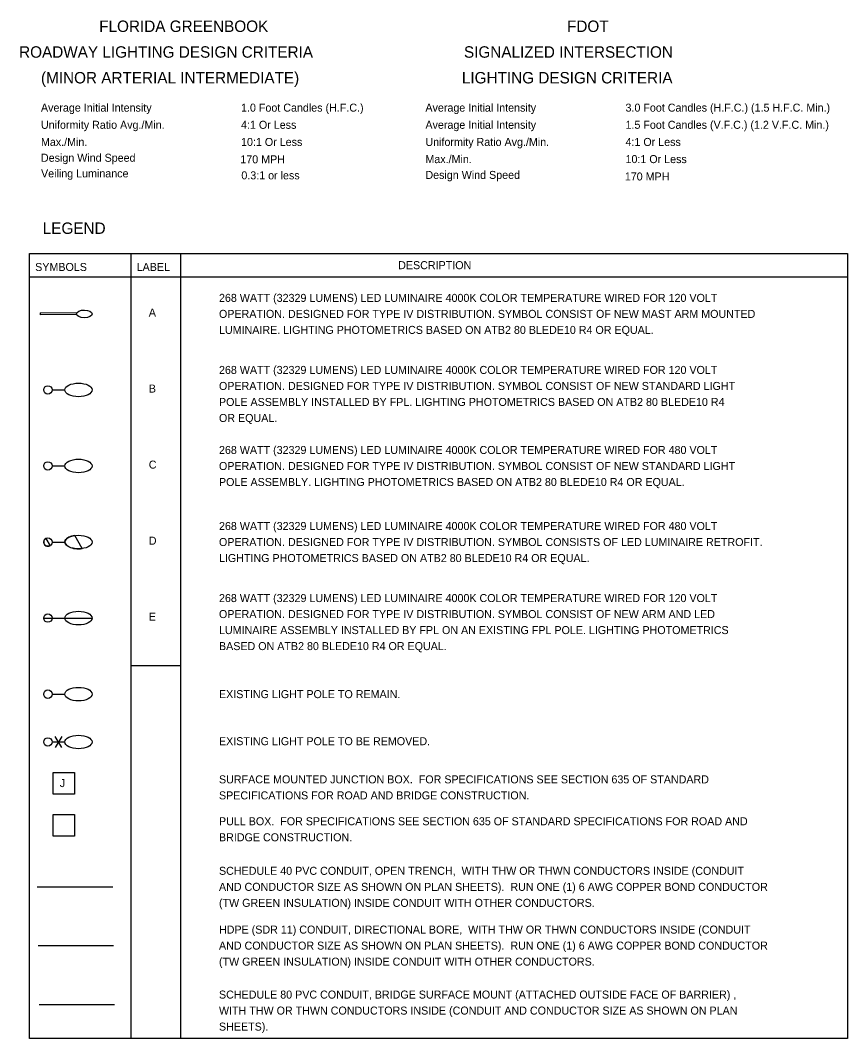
# Model space of a CAD drawing. Extents: x 0.1 to 21.4, y -0.2 to 9.3.
# Drawn here: x 0.15 to 7.38, y 0.37 to 9.27 of the extents above; entities that cross this region are included whole.
import ezdxf

# ---------------------------------------------------------------- set-up
doc = ezdxf.new("R2010")
doc.units = 0
for name, color, linetype in [('ConduitBM', 7, 'Continuous'), ('ConduitDB', 7, 'Continuous'), ('ConduitOT', 7, 'Continuous'), ('Luminaire', 7, 'Continuous'), ('PoleLight', 7, 'Continuous'), ('PoleLight_ep', 7, 'Continuous'), ('ScratchEle_dp', 7, 'Continuous'), ('SumBoxLines_dp', 7, 'Continuous'), ('TextLabel', 7, 'Continuous'), ('TextNotes', 7, 'Continuous')]:
    doc.layers.add(name, color=color, linetype=linetype)

msp = doc.modelspace()

# ---------------------------------------------------------------- linework, layer by layer
at = {"layer": 'ConduitBM'}
msp.add_line((0.3115, 0.6658), (0.9708, 0.6658), dxfattribs=at)
at = {"layer": 'ConduitDB'}
msp.add_line((0.3028, 1.1796), (0.9621, 1.1796), dxfattribs=at)
at = {"layer": 'ConduitOT'}
msp.add_line((0.294, 1.6935), (0.9534, 1.6935), dxfattribs=at)
at = {"layer": 'Luminaire'}
for p, q in [((0.3231, 6.6944), (0.3231, 6.713)), ((0.6391, 6.7089), (0.3231, 6.713)), ((0.6391, 6.6977), (0.3231, 6.6944))]:
    msp.add_line(p, q, dxfattribs=at)
msp.add_ellipse((0.7056, 6.7033), major_axis=(0.0675, -0.0001), ratio=0.5, dxfattribs=at)
at = {"layer": 'PoleLight'}
for p, q in [((0.4241, 6.0383), (0.5355, 6.0383)), ((0.4241, 5.3734), (0.5355, 5.3734)), ((0.3684, 4.7406), (0.4055, 4.6763)), ((0.6872, 4.6514), (0.6213, 4.7655)), ((0.4241, 4.7084), (0.5355, 4.7084)), ((0.3499, 4.0435), (0.4241, 4.0435)), ((0.4241, 4.0435), (0.5355, 4.0435)), ((0.5355, 4.0435), (0.7731, 4.0435))]:
    msp.add_line(p, q, dxfattribs=at)
for centre in [(0.387, 6.0383), (0.387, 5.3734), (0.387, 4.7084), (0.387, 4.0435)]:
    msp.add_circle(centre, 0.0371, dxfattribs=at)
msp.add_arc((0.387, 4.7084), 0.0371, 120.00004, 300.00004, dxfattribs=at)
for centre, major_axis in [((0.6543, 6.0383), (0.1188, 0)), ((0.6543, 5.3734), (0.1188, 0)), ((0.6543, 4.7084), (-0.1188, 0)), ((0.6543, 4.0435), (0.1188, 0))]:
    msp.add_ellipse(centre, major_axis=major_axis, ratio=0.5, dxfattribs=at)
msp.add_ellipse((0.6543, 4.7084), major_axis=(0.1188, 0), ratio=0.5, start_param=1.851831, end_param=4.993424, dxfattribs=at)
at = {"layer": 'PoleLight_ep'}
for p, q in [((0.4241, 3.3785), (0.5355, 3.3785)), ((0.4241, 2.96), (0.5355, 2.96)), ((0.5076, 2.9118), (0.4519, 3.0082)), ((0.5076, 3.0082), (0.4519, 2.9118))]:
    msp.add_line(p, q, dxfattribs=at)
for centre in [(0.387, 3.3785), (0.387, 2.96)]:
    msp.add_circle(centre, 0.0371, dxfattribs=at)
for centre in [(0.6543, 3.3785), (0.6543, 2.96)]:
    msp.add_ellipse(centre, major_axis=(0.1188, 0), ratio=0.5, dxfattribs=at)
at = {"layer": 'SumBoxLines_dp'}
for p, q in [((0.4319, 2.3255), (0.6194, 2.3255)), ((0.4319, 2.138), (0.4319, 2.3255)), ((0.6194, 2.3255), (0.6194, 2.138)), ((0.6194, 2.138), (0.4319, 2.138))]:
    msp.add_line(p, q, dxfattribs=at)
at = {"layer": 'TextNotes'}
for p, q in [((1.1131, 7.2325), (1.1131, 0.3662)), ((1.5493, 0.3662), (1.5493, 7.2325)), ((0.2258, 7.0287), (7.3816, 7.0287)), ((1.1131, 3.6278), (1.5493, 3.6278)), ((0.4319, 2.6918), (0.6194, 2.6918)), ((0.4319, 2.5043), (0.4319, 2.6918)), ((0.6194, 2.6918), (0.6194, 2.5043)), ((0.6194, 2.5043), (0.4319, 2.5043))]:
    msp.add_line(p, q, dxfattribs=at)
msp.add_lwpolyline([(0.2258, 7.2325), (7.3816, 7.2325), (7.3816, 0.3662), (0.2258, 0.3662)], close=True, dxfattribs=at)

# ---------------------------------------------------------------- texts
at = {"layer": 'ScratchEle_dp'}
for s, p in [('Veiling Luminance', (0.327, 7.8968)), ('0.3:1 or less', (2.0789, 7.8797))]:
    msp.add_text(s, height=0.07, dxfattribs=at).set_placement(p)
at = {"layer": 'TextLabel'}
for s, height, p in [('FLORIDA GREENBOOK', 0.1, (0.8357, 9.1683)), ('FDOT', 0.1, (4.927, 9.1683)), ('ROADWAY LIGHTING DESIGN CRITERIA', 0.1, (0.1351, 8.9433)), ('SIGNALIZED INTERSECTION', 0.1, (4.0259, 8.9433)), ('(MINOR ARTERIAL INTERMEDIATE)', 0.1, (0.3262, 8.7183)), ('LIGHTING DESIGN CRITERIA', 0.1, (4.0075, 8.7183)), ('SYMBOLS', 0.07, (0.2756, 7.0786)), ('LABEL', 0.07, (1.163, 7.0786)), ('DESCRIPTION', 0.07, (3.4503, 7.0943)), ('A', 0.07, (1.2694, 6.6803)), ('B', 0.07, (1.2694, 6.0153)), ('C', 0.07, (1.2694, 5.3504)), ('D', 0.07, (1.2694, 4.6855)), ('E', 0.07, (1.2694, 4.0205))]:
    msp.add_text(s, height=height, dxfattribs=at).set_placement(p)
at = {"layer": 'TextNotes'}
for s, height, p in [('Average Initial Intensity       ', 0.07, (0.3262, 8.4717)), ('1.0 Foot Candles (H.F.C.)', 0.07, (2.0762, 8.4717)), ('Average Initial Intensity       ', 0.07, (3.6888, 8.4717)), ('3.0 Foot Candles (H.F.C.) (1.5 H.F.C. Min.)', 0.07, (5.4388, 8.4717)), ('Uniformity Ratio Avg./Min.', 0.07, (0.3262, 8.3217)), ('4:1 Or Less', 0.07, (2.0762, 8.3217)), ('Average Initial Intensity       ', 0.07, (3.6888, 8.3217)), ('1.5 Foot Candles (V.F.C.) (1.2 V.F.C. Min.)', 0.07, (5.4388, 8.3217)), ('Max./Min.', 0.07, (0.3262, 8.1717)), ('10:1 Or Less', 0.07, (2.0762, 8.1717)), ('Uniformity Ratio Avg./Min.', 0.07, (3.6888, 8.1717)), ('4:1 Or Less', 0.07, (5.4388, 8.1717)), ('Design Wind Speed', 0.07, (0.3261, 8.0335)), ('170 MPH', 0.07, (2.0701, 8.0198)), ('Max./Min.', 0.07, (3.6888, 8.0217)), ('10:1 Or Less', 0.07, (5.4388, 8.0217)), ('Design Wind Speed', 0.07, (3.6887, 7.8835)), ('170 MPH', 0.07, (5.4327, 7.8698)), ('LEGEND', 0.1, (0.3418, 7.4026)), ('J', 0.07, (0.4908, 2.5656)), ('SURFACE MOUNTED JUNCTION BOX.  FOR SPECIFICATIONS SEE SECTION 635 OF STANDARD ', 0.07, (1.8832, 2.5981)), ('SPECIFICATIONS FOR ROAD AND BRIDGE CONSTRUCTION.', 0.07, (1.8832, 2.4581)), ('PULL BOX.  FOR SPECIFICATIONS SEE SECTION 635 OF STANDARD SPECIFICATIONS FOR ROAD AND', 0.07, (1.8832, 2.2318)), ('BRIDGE CONSTRUCTION.', 0.07, (1.8832, 2.0918)), ('SCHEDULE 40 PVC CONDUIT, OPEN TRENCH,  WITH THW OR THWN CONDUCTORS INSIDE (CONDUIT ', 0.07, (1.8832, 1.7985)), ('AND CONDUCTOR SIZE AS SHOWN ON PLAN SHEETS).  RUN ONE (1) 6 AWG COPPER BOND CONDUCTOR ', 0.07, (1.8832, 1.6585)), ('(TW GREEN INSULATION) INSIDE CONDUIT WITH OTHER CONDUCTORS.', 0.07, (1.8832, 1.5185)), ('HDPE (SDR 11) CONDUIT, DIRECTIONAL BORE,  WITH THW OR THWN CONDUCTORS INSIDE (CONDUIT ', 0.07, (1.8832, 1.2846)), ('AND CONDUCTOR SIZE AS SHOWN ON PLAN SHEETS).  RUN ONE (1) 6 AWG COPPER BOND CONDUCTOR ', 0.07, (1.8832, 1.1446)), ('(TW GREEN INSULATION) INSIDE CONDUIT WITH OTHER CONDUCTORS.', 0.07, (1.8832, 1.0046)), ('SCHEDULE 80 PVC CONDUIT, BRIDGE SURFACE MOUNT (ATTACHED OUTSIDE FACE OF BARRIER) , ', 0.07, (1.8832, 0.7165)), ('WITH THW OR THWN CONDUCTORS INSIDE (CONDUIT AND CONDUCTOR SIZE AS SHOWN ON PLAN ', 0.07, (1.8832, 0.5765)), ('SHEETS).  ', 0.07, (1.8832, 0.4365))]:
    msp.add_text(s, height=height, dxfattribs=at).set_placement(p)
for s, p in [('268 WATT (32329 LUMENS) LED LUMINAIRE 4000K COLOR TEMPERATURE WIRED FOR 120 VOLT ', (1.8832, 6.8083)), ('OPERATION. DESIGNED FOR TYPE IV DISTRIBUTION. SYMBOL CONSIST OF NEW MAST ARM MOUNTED ', (1.8832, 6.6683)), ('LUMINAIRE. LIGHTING PHOTOMETRICS BASED ON ATB2 80 BLEDE10 R4 OR EQUAL.', (1.8832, 6.5283)), ('268 WATT (32329 LUMENS) LED LUMINAIRE 4000K COLOR TEMPERATURE WIRED FOR 120 VOLT ', (1.8832, 6.1783)), ('OPERATION. DESIGNED FOR TYPE IV DISTRIBUTION. SYMBOL CONSIST OF NEW STANDARD LIGHT ', (1.8832, 6.0383)), ('POLE ASSEMBLY INSTALLED BY FPL. LIGHTING PHOTOMETRICS BASED ON ATB2 80 BLEDE10 R4 ', (1.8832, 5.8983)), ('OR EQUAL.', (1.8832, 5.7583)), ('268 WATT (32329 LUMENS) LED LUMINAIRE 4000K COLOR TEMPERATURE WIRED FOR 480 VOLT ', (1.8832, 5.4784)), ('OPERATION. DESIGNED FOR TYPE IV DISTRIBUTION. SYMBOL CONSIST OF NEW STANDARD LIGHT ', (1.8832, 5.3384)), ('POLE ASSEMBLY. LIGHTING PHOTOMETRICS BASED ON ATB2 80 BLEDE10 R4 OR EQUAL.', (1.8832, 5.1984)), ('268 WATT (32329 LUMENS) LED LUMINAIRE 4000K COLOR TEMPERATURE WIRED FOR 480 VOLT ', (1.8832, 4.8134)), ('OPERATION. DESIGNED FOR TYPE IV DISTRIBUTION. SYMBOL CONSISTS OF LED LUMINAIRE RETROFIT. ', (1.8832, 4.6734)), ('LIGHTING PHOTOMETRICS BASED ON ATB2 80 BLEDE10 R4 OR EQUAL.', (1.8832, 4.5334)), ('268 WATT (32329 LUMENS) LED LUMINAIRE 4000K COLOR TEMPERATURE WIRED FOR 120 VOLT ', (1.8832, 4.1835)), ('OPERATION. DESIGNED FOR TYPE IV DISTRIBUTION. SYMBOL CONSIST OF NEW ARM AND LED ', (1.8832, 4.0435)), ('LUMINAIRE ASSEMBLY INSTALLED BY FPL ON AN EXISTING FPL POLE. LIGHTING PHOTOMETRICS ', (1.8832, 3.9035)), ('BASED ON ATB2 80 BLEDE10 R4 OR EQUAL.', (1.8832, 3.7635)), ('EXISTING LIGHT POLE TO REMAIN.', (1.8832, 3.3435)), ('EXISTING LIGHT POLE TO BE REMOVED.', (1.8832, 2.932))]:
    msp.add_text(s, height=0.07, rotation=360, dxfattribs=at).set_placement(p)

doc.saveas('drawing.dxf')
